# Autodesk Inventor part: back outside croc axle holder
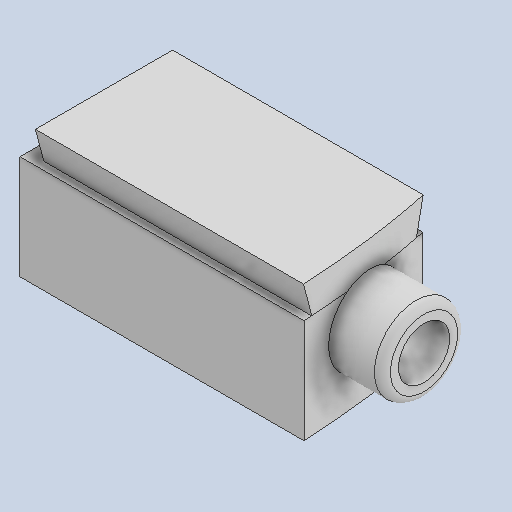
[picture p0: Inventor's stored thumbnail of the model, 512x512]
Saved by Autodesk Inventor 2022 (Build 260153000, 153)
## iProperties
Created: 2021-07
Part Number: back outside croc axle holder
Material: Generic
Document SubType Name: Modeling
Designer: garre
Density: 1 g/cm^3
Appearance: Default
Author: garre
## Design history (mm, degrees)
derived "croc skate axle holders.ipt"
feature "back outside::croc skate axle holders.ipt" dims "d0" = 10
tag "TaggingFeature1"
body "Solid1"
